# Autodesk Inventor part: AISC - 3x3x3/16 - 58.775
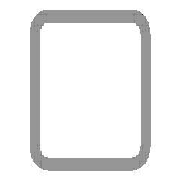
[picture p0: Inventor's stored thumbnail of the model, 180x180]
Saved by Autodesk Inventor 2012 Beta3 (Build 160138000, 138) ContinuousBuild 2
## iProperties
_CCFamilyMember: 9
_CCFamilyDisplayName: ANSI AISC (Square) - Tube
_FrameMemberDoc: Frame Member File
_Version: 15.0.0
_GetPNFromCC: 1
Created: 2011-01
Part Number: AISC - 3x3x3/16 - 58.775
Material: Steel, Mild
Description: Tube
Document SubType Name: Modeling
Standard: ANSI
Designer: Beta-8540w
Standards Organization: ANSI
Language: en-US
Size Designation: 3x3x3/16
Categories: <MemberInstance><Categories><Category DisplayName="Structural Shapes" InternalName="089c4875-fa83-4c05-b084-43b9cc11f5ed" Mnemonic="GRDR"><CategoryParameter Dis
Stock Number: 3x3x3/16
Density: 7.86 g/cm^3
IsCustomPart: 1
G_L: 58.775 in
G_W: 3.000 in
G_H: 3.000 in
+5F3B86C3-FC7A-4F54-B2FE-F4D1CEC6511F+CUTDETAIL1: Cut
Author: Beta-8540w
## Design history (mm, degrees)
node "Start plane"
node "End plane"
sketch "Sketch"
  geometry: L1 (-38.1, -28.575)-(-38.1, 28.575); L2 (-28.575, 38.1)-(28.575, 38.1); L3 (38.1, 28.575)-(38.1, -28.575); L4 (28.575, -38.1)-(-28.575, -38.1); L5 (-28.575, 33.337)-(28.575, 33.338); L6 (33.338, 28.575)-(33.338, -28.575); L7 (28.575, -33.337)-(-28.575, -33.338); L8 (-33.338, -28.575)-(-33.338, 28.575); L9 (0, 56.102)-(0, -56.102) reference; L10 (-56.102, 0)-(56.102, 0) reference; A1 r 9.525 centre (-28.575, -28.575) between (-38.1, -28.575) and (-28.575, -38.1); A2 r 9.525 centre (-28.575, 28.575) between (-28.575, 38.1) and (-38.1, 28.575); A3 r 9.525 centre (28.575, 28.575) between (38.1, 28.575) and (28.575, 38.1); A4 r 9.525 centre (28.575, -28.575) between (28.575, -38.1) and (38.1, -28.575); A5 r 4.763 centre (-28.575, 28.575) between (-28.575, 33.337) and (-33.338, 28.575); A6 r 4.763 centre (28.575, 28.575) between (33.338, 28.575) and (28.575, 33.338); A7 r 4.763 centre (28.575, -28.575) between (28.575, -33.337) and (33.338, -28.575); A8 r 4.763 centre (-28.575, -28.575) between (-33.338, -28.575) and (-28.575, -33.338)
  constraints: 16 end point, 16 point on circle, 8 centre point, 8 tangent, 4 parallel, 3 equal radius, 2 perpendicular, 7 other
  dimensions: "d10" = 76.2 distance between parallel lines of L2 L4 (= G_H); "d11" = 76.2 distance between parallel lines of L1 L3 (= G_W); "d12" = 4.7625 distance between parallel lines of L3 L6 (= G_T); "d15" = 38.1 distance between parallel lines of L2 L10 (= 0.5 x d10); "d16" = 38.1 distance between parallel lines of L9 L3 (= 0.5 x d11); "d17" = 9.525 radius of A1 (= G_IR)
extrude "Body" new body sketch "Sketch" stored distance "d3" = 1492.89148 (= G_L); taper "d4" = 0 deg
node "Driven Length"
  sketch "Sketch3"
    geometry: L1 (0, 0)-(10, 0) reference
    constraints: 2 end point, 1 horizontal
  workplane "Work Plane3"
  sketch "Sketch4"
    geometry: L1 (-2, 0)-(12, 0) reference; L2 (-2, 1492.891)-(12, 1492.891) reference
    dimensions: "d19" = 1492.89148 distance between parallel lines of L1 L2 (derived)
workplane "Work Plane4"
split "Split1"
body "Solid1"
other parameters: "G_W" = 76.2 [user parameter; used in 1 equation term], "G_H" = 76.2 [user parameter; used in 1 equation term], "G_T" = 4.7625 [user parameter; used in 1 equation term], "G_IR" = 9.525 [user parameter; used in 1 equation term], "G_L" = 1492.89148 (= d19) [user parameter; used in 1 equation term], "G_OFFSET_START" = 0 [user parameter; used in 1 equation term], "G_OFFSET_END" = -31.10852 [user parameter; used in 1 equation term], "d13" = 0 (computed from G_OFFSET_START), "d14" = 1492.89148 (= G_OFFSET_END + B_L), "B_L" = 1524 [user parameter; used in 1 equation term], "d18" = 90 deg
